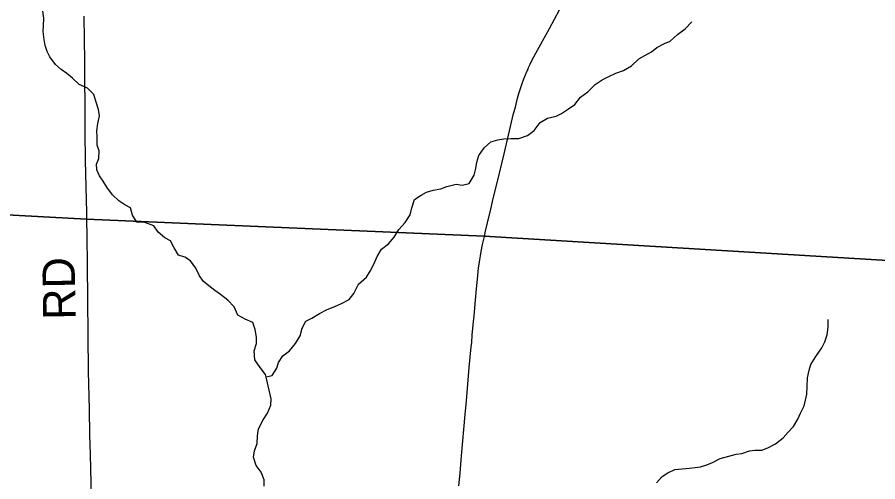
# Model space of a CAD drawing. Extents: x 0 to 34, y 0 to 22.
# Drawn here: x 4.698 to 6.205, y 14.889 to 15.703 of the extents above; entities that cross this region are included whole.
import ezdxf

# ---------------------------------------------------------------- set-up
doc = ezdxf.new("R2010")
doc.units = 0
for name, color, linetype in [('Default', 7, 'Continuous'), ('GM_X_Minor_River', 7, 'Continuous'), ('GM_X_State_Route', 7, 'Continuous'), ('GM_X_Township_Road', 7, 'Continuous'), ('GM_X_Township_Road_Text', 7, 'Continuous')]:
    doc.layers.add(name, color=color, linetype=linetype)

msp = doc.modelspace()

# ---------------------------------------------------------------- linework, layer by layer
at = {"layer": 'Default'}
msp.add_lwpolyline([(3.47, 19.2407), (3.2768, 17.1355), (3.2667, 16.919), (3.1974, 16.1596), (3.1343, 15.4291), (3.1796, 15.4266), (4.2078, 15.3826), (4.2393, 15.3805), (4.819, 15.349), (5.5157, 15.319), (7.9465, 15.1727), (8.1234, 15.1688), (8.137, 15.3372), (8.146, 15.4642), (8.2031, 16.209), (8.2895, 16.85), (8.3286, 17.3076), (8.3307, 17.3314), (8.3334, 17.361), (8.3935, 18.0719)], dxfattribs=at)
msp.add_lwpolyline([(2.9696, 13.6252), (8.4279, 13.6252), (8.4024, 15.1386), (8.4023, 15.1576), (8.3761, 15.1587), (8.1234, 15.1688), (7.9465, 15.1727), (5.5157, 15.319), (4.819, 15.349), (4.2393, 15.3805), (4.2078, 15.3826), (3.1796, 15.4266), (3.1343, 15.4291), (3.0617, 14.6751), (3.0457, 14.4958), (3.0429, 14.4692)], close=True, dxfattribs=at)
at = {"layer": 'GM_X_Minor_River'}
for points in [[(4.7649, 15.6197), (4.7549, 15.6332), (4.7498, 15.6428), (4.7466, 15.6531), (4.745, 15.6633), (4.743, 15.6778), (4.7435, 15.6873), (4.7442, 15.7009), (4.7426, 15.7131)], [(5.1336, 15.0729), (5.144, 15.075), (5.1522, 15.0877), (5.1554, 15.0975), (5.1629, 15.1095), (5.1744, 15.1184), (5.1849, 15.1311), (5.1931, 15.1446), (5.1968, 15.1578), (5.2035, 15.1702), (5.2138, 15.1753), (5.2273, 15.1837), (5.2407, 15.1907), (5.254, 15.1957), (5.2655, 15.2012), (5.2789, 15.2081), (5.2875, 15.2186), (5.2954, 15.2351), (5.3093, 15.2474), (5.3159, 15.2575), (5.3226, 15.2702), (5.3282, 15.2834), (5.3357, 15.2965), (5.348, 15.3058), (5.3581, 15.317), (5.3659, 15.3305), (5.3772, 15.3428), (5.3858, 15.3566), (5.3887, 15.3687), (5.3939, 15.383), (5.4051, 15.3908), (5.4146, 15.3959), (5.4265, 15.3994), (5.4398, 15.4022), (5.4505, 15.4058), (5.4665, 15.41), (5.477, 15.4083), (5.4896, 15.4115), (5.4982, 15.4257), (5.5011, 15.4374), (5.5029, 15.4484), (5.5065, 15.4605), (5.5159, 15.4735), (5.5271, 15.4843), (5.5396, 15.4875), (5.5499, 15.4896), (5.5624, 15.4901), (5.5765, 15.4902), (5.5917, 15.4956), (5.6033, 15.5044), (5.6138, 15.5183), (5.6268, 15.526), (5.6417, 15.5291), (5.6512, 15.5342), (5.6635, 15.5419), (5.6747, 15.5497), (5.6844, 15.5628), (5.6975, 15.5716), (5.7099, 15.5846), (5.7222, 15.5927), (5.734, 15.5986), (5.7466, 15.6044), (5.76, 15.6091), (5.7738, 15.6175), (5.7866, 15.6294), (5.7969, 15.6356), (5.8088, 15.6422), (5.8184, 15.6496), (5.8318, 15.6566), (5.8414, 15.6606), (5.8545, 15.6724), (5.868, 15.682), (5.8796, 15.6947)], [(5.1302, 14.881), (5.1304, 14.892), (5.125, 14.9058), (5.1165, 14.9173), (5.1115, 14.9318), (5.1136, 14.9428), (5.1177, 14.9556), (5.1183, 14.9693), (5.1201, 14.9814), (5.1284, 14.9971), (5.1362, 15.0088), (5.1421, 15.0227), (5.1424, 15.034), (5.1372, 15.0569), (5.1351, 15.0672), (5.1326, 15.0767), (5.1234, 15.0887), (5.1138, 15.1025), (5.1127, 15.1181), (5.1167, 15.1309), (5.1169, 15.1423), (5.1142, 15.1556), (5.1106, 15.1678), (5.0971, 15.1738), (5.0844, 15.1809), (5.0775, 15.1954), (5.0664, 15.207), (5.0537, 15.2168), (5.044, 15.2238), (5.0335, 15.2323), (5.0235, 15.2401), (5.0168, 15.2497), (5.0103, 15.2628), (5.0011, 15.2759), (4.9914, 15.2821), (4.9804, 15.2858), (4.9724, 15.2984), (4.9662, 15.3107), (4.9564, 15.3162), (4.9445, 15.3263), (4.9372, 15.3374), (4.921, 15.3427), (4.9074, 15.3437), (4.8993, 15.356), (4.8958, 15.3686), (4.886, 15.3737), (4.8759, 15.3808), (4.8644, 15.3912), (4.8548, 15.4051), (4.8482, 15.4151), (4.8416, 15.4247), (4.8369, 15.435), (4.8363, 15.4449), (4.8407, 15.4551), (4.841, 15.4683), (4.8378, 15.4783), (4.8377, 15.4931), (4.8372, 15.5037), (4.8389, 15.5162), (4.8415, 15.5298), (4.8398, 15.5412), (4.8356, 15.5557), (4.8316, 15.5672), (4.8205, 15.578), (4.8059, 15.5847), (4.7943, 15.5956), (4.7846, 15.6038), (4.7746, 15.6112), (4.7649, 15.6197)], [(5.8179, 14.8867), (5.8273, 14.8983), (5.8376, 14.9042), (5.8499, 14.9104), (5.8624, 14.9113), (5.8753, 14.9129), (5.8852, 14.9138), (5.8947, 14.9148), (5.9042, 14.9176), (5.9145, 14.922), (5.9294, 14.9293), (5.9443, 14.9339), (5.9573, 14.9371), (5.9671, 14.9384), (5.9805, 14.9427), (5.99, 14.944), (6.0021, 14.9441), (6.0128, 14.9481), (6.0262, 14.955), (6.0397, 14.9658), (6.0482, 14.9755), (6.0579, 14.9855), (6.0654, 14.9983), (6.0701, 15.0088), (6.0765, 15.022), (6.0789, 15.0318), (6.081, 15.042), (6.0817, 15.0556), (6.082, 15.0708), (6.0849, 15.0844), (6.0882, 15.0942), (6.0968, 15.1084), (6.107, 15.1234), (6.1125, 15.1339), (6.1169, 15.1463), (6.1183, 15.1596), (6.1186, 15.1729)]]:
    msp.add_lwpolyline(points, dxfattribs=at)
at = {"layer": 'GM_X_State_Route'}
for points in [[(5.5925, 15.6118), (5.5936, 15.6143), (5.5964, 15.6206), (5.5989, 15.6256), (5.6061, 15.6394), (5.6302, 15.6831), (5.6476, 15.7155), (5.6605, 15.7395), (5.6682, 15.7544), (5.6723, 15.7631), (5.6753, 15.7697), (5.6774, 15.775), (5.6799, 15.7816), (5.6863, 15.8005), (5.7097, 15.8726), (5.7276, 15.9276), (5.7346, 15.9493), (5.7391, 15.9631), (5.7434, 15.9758), (5.7489, 15.9933), (5.7529, 16.0068), (5.7556, 16.0156), (5.7582, 16.0249)], [(5.5305, 15.38), (5.5339, 15.3945), (5.5382, 15.4124), (5.5505, 15.463), (5.5581, 15.4959), (5.5673, 15.5339), (5.5703, 15.5451), (5.5743, 15.5605), (5.5767, 15.5689), (5.581, 15.5831), (5.5829, 15.5885), (5.5853, 15.5949), (5.588, 15.6014), (5.591, 15.6084), (5.5925, 15.6118)], [(5.516, 15.3185), (5.5181, 15.3276), (5.5216, 15.3424), (5.5274, 15.3665), (5.5305, 15.38)], [(5.4716, 14.8814), (5.4735, 14.9038), (5.476, 14.9342), (5.4824, 15.0064), (5.4846, 15.0308), (5.4897, 15.0891), (5.4931, 15.125), (5.4938, 15.1329), (5.4949, 15.1456), (5.4965, 15.1637), (5.4979, 15.1796), (5.5003, 15.2069), (5.5021, 15.2268), (5.5038, 15.2435), (5.5051, 15.2564), (5.5059, 15.2636), (5.5069, 15.2701), (5.508, 15.2773), (5.5092, 15.2847), (5.5105, 15.2921), (5.5129, 15.3044), (5.516, 15.3185)]]:
    msp.add_lwpolyline(points, dxfattribs=at)
at = {"layer": 'GM_X_Township_Road'}
for points in [[(4.8193, 15.3485), (4.8193, 15.3611), (4.8184, 15.405), (4.8174, 15.452), (4.8169, 15.4999), (4.8164, 15.5526), (4.8161, 15.5891), (4.8158, 15.6263), (4.8154, 15.6633), (4.815, 15.7046)], [(4.8363, 14.5184), (4.8356, 14.5326), (4.8352, 14.5452), (4.8349, 14.563), (4.8347, 14.5727), (4.8344, 14.5856), (4.8336, 14.6173), (4.8324, 14.6629), (4.8319, 14.6816), (4.8312, 14.7132), (4.8296, 14.7797), (4.8292, 14.8002), (4.8283, 14.8431), (4.8269, 14.8878), (4.8259, 14.9357), (4.8251, 14.9717), (4.8242, 15.0154), (4.8227, 15.0828), (4.8213, 15.2078), (4.8208, 15.2684), (4.8201, 15.3196), (4.8193, 15.3485)]]:
    msp.add_lwpolyline(points, dxfattribs=at)

# ---------------------------------------------------------------- texts
at = {"layer": 'GM_X_Township_Road_Text'}
msp.add_text('RD', height=0.05682, rotation=90.9835, dxfattribs=at).set_placement((4.8, 15.173))

doc.saveas('drawing.dxf')
